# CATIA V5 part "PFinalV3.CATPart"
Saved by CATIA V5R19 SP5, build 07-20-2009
Part number: PeçaFinal
Bounding box of the stored display mesh (mm): x -39 to 2, y -77 to 65.5, z -65.329 to 80.065
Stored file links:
  Z:\UA\ATLAS\atlascar\ServoPiloto\dir\PFinalV3.CATPart
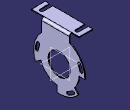
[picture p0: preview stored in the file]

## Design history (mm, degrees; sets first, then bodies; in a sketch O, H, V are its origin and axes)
SheetMetalParameters1: Thickness 2, BendRadius 4, KFactor 0.400515 {= log(min(100,max(20*SheetMetalParameters1.BendRadius,SheetMetalParameters1.Thickness)/SheetMetalParameters1.Thickness))/log(100)/2}, ReliefRadialLength 1, ReliefAxialLength 2, MinimumBendRadius 0
Body1 (main body)
  Sketch1 on yz-plane, origin (0, 0, 0), H (0, 1, 0), V (0, 0, 1)
    circle A1 centre (0, 0) radius 28.5
    circle A2 centre (0, 0) radius 65.5
    construction circle A3 centre (0, 0) radius 57.5
    construction line L1 (0, 0) -> (102.6508, 37.3618)
    point P1 (0, 0)
    construction line L2 (0, 0) -> (-87.8315, 20.2775)
    construction line L3 (0, 0) -> (59.7099, -95.5558)
    construction arc A4 centre (0, 0) radius 57.5 from (56.2235, 12.0488) to (51.1939, 26.1808) ccw
    point P5 (51.1939, 26.1808)
    point P6 (56.2235, 12.0488)
    arc A5 centre (56.2235, 12.0488) radius 4 from (60.1347, 12.8869) to (52.3123, 11.2106) cw
    arc A6 centre (51.1939, 26.1808) radius 4 from (47.6326, 24.3595) to (54.7552, 28.0021) cw
    arc A7 centre (0, 0) radius 53.5 from (52.3123, 11.2106) to (47.6326, 24.3595) ccw
    arc A8 centre (0, 0) radius 61.5 from (54.7552, 28.0021) to (60.1347, 12.8869) cw
    construction arc A9 centre (0, 0) radius 57.5 from (-54.2431, 19.0772) to (-57.3315, 4.3986) ccw
    point P11 (-54.2431, 19.0772)
    point P12 (-57.3315, 4.3986)
    arc A10 centre (-54.2431, 19.0772) radius 4 from (-58.0165, 20.4043) to (-50.4696, 17.7501) cw
    arc A11 centre (-57.3315, 4.3986) radius 4 from (-53.3432, 4.0926) to (-61.3198, 4.7046) cw
    arc A12 centre (0, 0) radius 53.5 from (-50.4696, 17.7501) to (-53.3432, 4.0926) ccw
    arc A13 centre (0, 0) radius 61.5 from (-61.3198, 4.7046) to (-58.0165, 20.4043) cw
    construction arc A14 centre (0, 0) radius 57.5 from (22.6644, -52.8448) to (35.5611, -45.1847) ccw
    point P17 (22.6644, -52.8448)
    point P18 (35.5611, -45.1847)
    arc A15 centre (22.6644, -52.8448) radius 4 from (24.2411, -56.521) to (21.0878, -49.1687) cw
    arc A16 centre (35.5611, -45.1847) radius 4 from (33.0872, -42.0415) to (38.0349, -48.328) cw
    arc A17 centre (0, 0) radius 53.5 from (21.0878, -49.1687) to (33.0872, -42.0415) ccw
    arc A18 centre (0, 0) radius 61.5 from (38.0349, -48.328) to (24.2411, -56.521) cw
    radius A1 = 28.5
    radius A2 = 65.5
    radius A3 = 57.5
    angle L1 H = 20
    angle H L2 = 13
    radius A6 = 4
    radius A11 = 4
    radius A16 = 4
    distance L2 P11 = 6.3862
    distance P12 L2 = 8.6109
    distance L1 P5 = 7.0926
    distance P6 L1 = 7.9074
    distance L3 P18 = 6.2132
    distance P17 L3 = 8.783
    angle H L3 = 58
    coincidence: P1 H, P5 A3, P11 A3, P17 A3, P1 O
    tangency: A7 A6, A6 A8, A8 A5, A5 A7, A12 A11, A11 A13, A13 A10, A10 A12, A17 A16, A16 A18, A18 A15, A15 A17
    concentricity: A7 O, A8 O, A12 O, A13 O, A17 O, A18 O
  Pad1: profile Sketch1, direction (1, 0, 0), length 2
  Sketch2 on end face of Pad1, origin (2, 0, 0), H (0, 1, 0), V (0, 0, 1)
    line L1 (-45, 109.0648) -> (26, 109.0648)
    line L2 (26, 109.0648) -> (26, 29.0648)
    line L3 (26, 29.0648) -> (-45, 29.0648)
    line L4 (-45, 29.0648) -> (-45, 109.0648)
    distance H L3 = 29.0648
    length L2 = 80
    distance V L2 = 26
    distance V L4 = 45
    horizontal: L1 H, L3 H
    vertical: L2 V, L4 V
  Pad2: profile Sketch2, direction (1, 0, 0), up to start face of Pad1
  Sketch3 on face of Pad2 from Sketch2.L4, origin (0, -45, 0), H (1, 0, 0), V (0, 0, 1)
    line L1 (0, 74.0648) -> (0, 109.0648)
    line L2 (0, 109.0648) -> (2, 109.0648)
    line L3 (2, 109.0648) -> (2, 74.0648)
    line L4 (0, 74.0648) -> (2, 74.0648)
    distance L2 L4 = 35
    distance H L4 = 74.0648
    length L2 = 2
    distance L1 V = 0
    horizontal: L4 H
    vertical: L3 V
  Pad3: profile Sketch3, direction (0, -1, 0), length 28, opposite side length 100
  Sketch4 on face of Pad3, origin (2, 0, 0), H (0, 1, 0), V (0, 0, 1)
    arc A1 centre (29, 87.0648) radius 4.5 from (24.5, 87.0648) to (33.5, 87.0648) ccw
    point P1 (29, 87.0648)
    arc A2 centre (-53, 87.0648) radius 4.5 from (-57.5, 87.0648) to (-48.5, 87.0648) ccw
    point P2 (-53, 87.0648)
    reference projected line E1 (26, 109.0648) -> (-45, 109.0648) from edge [face of Pad3 | face of Pad3]
    reference projected line E2 (26, 109.0648) -> (-45, 109.0648) from edge [face of Pad3 | face of Pad3]
    line L1 (33.5, 87.0648) -> (33.5, 115.8082)
    point P3 (33.5, 87.0648)
    line L2 (24.5, 87.0648) -> (24.5, 115.8082)
    point P5 (24.5, 87.0648)
    line L3 (-48.5, 87.0648) -> (-48.5, 115.8082)
    point P7 (-48.5, 87.0648)
    line L4 (-57.5, 87.0648) -> (-57.5, 115.8082)
    point P9 (-57.5, 87.0648)
    line L5 (24.5, 115.8082) -> (33.5, 115.8082)
    line L6 (-57.5, 115.8082) -> (-48.5, 115.8082)
    point P11 (24.5, 87.0648)
    point P12 (33.5, 87.0648)
    point P13 (-57.5, 87.0648)
    point P14 (-48.5, 87.0648)
    radius A2 = 4.5
    radius A1 = 4.5
    distance P2 E1 = 22
    distance P1 E2 = 22
    distance V P1 = 29
    distance P2 P1 = 82
    coincidence: P3 A1, P5 A1, P7 A2, P9 A2, L1 P12, L2 P11, L3 P14, L4 P13, P3 P12, P5 P11, P7 P14, P9 P13
    tangency: L1 A1, L2 A1, L3 A2, L4 A2
    horizontal: L5 H, L6 H
  Pocket1: profile Sketch4, direction (-1, 0, 0), through (limit type 3)
  Split1: SplitPlane face of Pad3 from Sketch3.L4
  Recognize1: Recognize_BendTable SheetMetalParameters1, Recognize_ReferenceFace face of Pad3, KFacteur 0.400515 {= SheetMetalParameters1.KFactor}
  Flange1: Angle 90, Length 35, Radius 4, KFacteur 0.400515 {= log(min(100,max(20*Flange1.Radius,SheetMetalParameters1.Thickness)/SheetMetalParameters1.Thickness))/log(100)/2}, Guide edge [face of Recognize1 | face of Recognize1]
  Sketch5 on face of Flange1, origin (0, -45, 0), H (1, 0, 0), V (0, 0, 1)
    line L1 (-4, 78.0648) -> (-39, 78.0648)
    line L2 (-39, 78.0648) -> (-39, 80.0648)
    line L3 (-39, 80.0648) -> (-4, 80.0648)
    line L4 (-4, 78.0648) -> (-4, 80.0648)
    reference projected line E1 (-4, 80.0648) -> (-39, 80.0648) from edge [face of Flange1 | face of Flange1]
    reference projected line E2 (-4, 78.0648) -> (-39, 78.0648) from edge [face of Flange1 | face of Flange1]
    reference intersected line E3 (-39, 78.0648) -> (-39, 80.0648) from face of Flange1
    distance L2 L4 = 35
    horizontal: L3 H
    coincidence: L3 E1, L1 E2, L2 E3
  Pad4: profile Sketch5, direction (0, -1, 0), length 32, opposite side length 90
  Sketch6 on face of Pad4, origin (-74.0648, 0, 78.0648), H (0, 1, 0), V (1, 0, 0)
    arc A1 centre (-62, 59.0648) radius 4.5 from (-57.5, 59.0648) to (-66.5, 59.0648) ccw
    point P1 (-62, 59.0648)
    arc A2 centre (29, 59.0648) radius 4.5 from (33.5, 59.0648) to (24.5, 59.0648) ccw
    point P2 (29, 59.0648)
    line L1 (-66.5, 59.0648) -> (-66.5, 30.3215)
    point P3 (-66.5, 59.0648)
    line L2 (-57.5, 59.0648) -> (-57.5, 30.3215)
    point P5 (-57.5, 59.0648)
    line L3 (24.5, 59.0648) -> (24.5, 35.0648)
    point P7 (24.5, 59.0648)
    line L4 (33.5, 59.0648) -> (33.5, 35.0648)
    point P9 (33.5, 59.0648)
    line L5 (-57.5, 30.3215) -> (-66.5, 30.3215)
    line L6 (33.5, 35.0648) -> (24.5, 35.0648)
    point P11 (-57.5, 59.0648)
    point P12 (-66.5, 59.0648)
    point P13 (33.5, 59.0648)
    point P14 (24.5, 59.0648)
    reference projected line E1 (26, 35.0648) -> (-45, 35.0648) from edge [face of Pad4 | face of Pad4]
    radius A2 = 4.5
    radius A1 = 4.5
    distance P2 P1 = 91
    length L3 = 24
    distance P2 V = 29
    coincidence: P3 A1, P5 A1, P7 A2, P9 A2, L1 P12, L2 P11, L3 P14, L4 P13, P3 P12, P5 P11, P7 P14, P9 P13, L6 E1
    tangency: L1 A1, L2 A1, L3 A2, L4 A2
    vertical: L3 V, L4 V
  Pocket2: profile Sketch6, direction (0, 0, 1), through (limit type 3)
  Sketch7 on face of Recognize1, origin (0, 0, 0), H (0, -1, 0), V (0, 0, 1)
    arc A1 centre (0, 0) radius 49.0455 from (4.724, -48.8175) to (46.8718, -14.4394) ccw
    line L1 (46.8718, -14.4394) -> (81.591, -37.4888)
    line L2 (81.591, -37.4888) -> (4.724, -86.9825)
    line L3 (4.724, -86.9825) -> (4.724, -48.8175)
    arc A2 centre (0, 0) radius 50.5673 from (-50.5547, -1.131) to (-38.7521, -32.4858) ccw
    line L4 (-50.5547, -1.131) -> (-91.49, -1.131)
    line L5 (-91.49, -1.131) -> (-66.8429, -63.7544)
    line L6 (-66.8429, -63.7544) -> (-38.7521, -32.4858)
    vertical: L3 V
    horizontal: L4 H
  Pocket3: profile Sketch7, direction (1, 0, 0), through (limit type 3)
